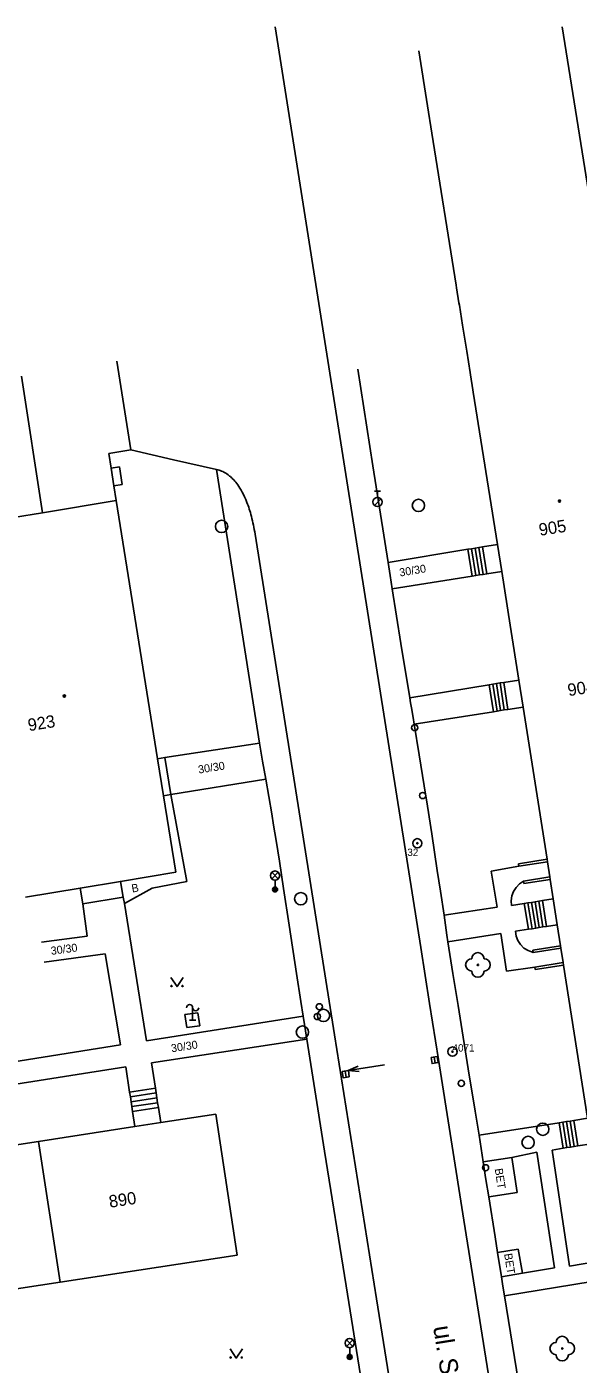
# Model space of a CAD drawing. Extents: x -539244 to -537359, y -1183785 to -1181851.
# Drawn here: x -537635.9 to -537591.1, y -1181981.5 to -1181872.9 of the extents above; entities that cross this region are included whole.
import ezdxf

# ---------------------------------------------------------------- set-up
doc = ezdxf.new("R2010")
doc.units = 0
for name, color, linetype in [('Vrstva 10', 7, 'Continuous'), ('Vrstva 11', 7, 'Continuous'), ('Vrstva 21', 7, 'Continuous'), ('Vrstva 22', 7, 'Continuous'), ('Vrstva 23', 7, 'Continuous'), ('Vrstva 24', 7, 'Continuous'), ('Vrstva 27', 7, 'Continuous'), ('Vrstva 28', 7, 'Continuous'), ('Vrstva 33', 7, 'Continuous'), ('Vrstva 36', 7, 'Continuous'), ('Vrstva 39', 7, 'Continuous'), ('Vrstva 40', 7, 'Continuous'), ('Vrstva 45', 7, 'Continuous'), ('Vrstva 47', 7, 'Continuous'), ('Vrstva 49', 7, 'Continuous'), ('Vrstva 5', 7, 'Continuous'), ('Vrstva 7', 7, 'Continuous')]:
    doc.layers.add(name, color=color, linetype=linetype)

msp = doc.modelspace()

# ---------------------------------------------------------------- linework, layer by layer
at = {"layer": 'Vrstva 10'}
for p, q in [((-537609.825, -1181910.265), (-537615.74, -1181872.87)), ((-537603.91, -1181947.66), (-537609.825, -1181910.265)), ((-537614.135, -1181934.425), (-537617.36, -1181914.09)), ((-537610.91, -1181954.76), (-537614.135, -1181934.425)), ((-537622, -1181952.95), (-537623.06, -1181953.1)), ((-537623.06, -1181953.1), (-537622.91, -1181954.16)), ((-537621.85, -1181954.01), (-537622, -1181952.95)), ((-537622.91, -1181954.16), (-537621.85, -1181954.01)), ((-537607.495, -1181976.195), (-537610.91, -1181954.76)), ((-537601.447, -1181963.276), (-537602.48, -1181956.74)), ((-537600.408, -1181969.81), (-537601.447, -1181963.276)), ((-537598.321, -1181982.879), (-537600.408, -1181969.81)), ((-537604.08, -1181997.63), (-537607.495, -1181976.195))]:
    msp.add_line(p, q, dxfattribs=at)
for points in [[(-537620.49, -1181908.83), (-537623.975, -1181908.035), (-537627.46, -1181907.24)], [(-537617.36, -1181914.09), (-537617.391, -1181913.899), (-537617.425, -1181913.71), (-537617.46, -1181913.524), (-537617.497, -1181913.341), (-537617.535, -1181913.162), (-537617.575, -1181912.988), (-537617.616, -1181912.817), (-537617.658, -1181912.652), (-537617.701, -1181912.491), (-537617.746, -1181912.336), (-537617.79, -1181912.185), (-537617.836, -1181912.04), (-537617.882, -1181911.9), (-537617.929, -1181911.765), (-537617.976, -1181911.635), (-537618.023, -1181911.51), (-537618.119, -1181911.27), (-537618.215, -1181911.051), (-537618.311, -1181910.849), (-537618.406, -1181910.665), (-537618.5, -1181910.497), (-537618.591, -1181910.344), (-537618.681, -1181910.205), (-537618.768, -1181910.079), (-537618.853, -1181909.964), (-537618.935, -1181909.86), (-537619.014, -1181909.766), (-537619.09, -1181909.681), (-537619.163, -1181909.603), (-537619.234, -1181909.533), (-537619.301, -1181909.47), (-537619.366, -1181909.413), (-537619.427, -1181909.361), (-537619.546, -1181909.269), (-537619.653, -1181909.194), (-537619.749, -1181909.133), (-537619.835, -1181909.082), (-537619.912, -1181909.041), (-537619.98, -1181909.007), (-537620.102, -1181908.953), (-537620.196, -1181908.917), (-537620.268, -1181908.892), (-537620.378, -1181908.858), (-537620.49, -1181908.83)], [(-537602.48, -1181956.74), (-537603.195, -1181952.2), (-537603.91, -1181947.66)]]:
    msp.add_lwpolyline(points, dxfattribs=at)
at = {"layer": 'Vrstva 11'}
for p, q in [((-537607.796, -1181908.535), (-537609.03, -1181900.69)), ((-537629.06, -1181908.728), (-537628.37, -1181908.62)), ((-537628.16, -1181910.04), (-537628.37, -1181908.62)), ((-537617.01, -1181931.05), (-537620.49, -1181908.83)), ((-537606.56, -1181916.38), (-537607.796, -1181908.535)), ((-537628.837, -1181910.146), (-537628.16, -1181910.04)), ((-537600.09, -1181915.31), (-537606.56, -1181916.38)), ((-537599.743, -1181917.49), (-537600.09, -1181915.31)), ((-537599.446, -1181917.442), (-537599.793, -1181915.262)), ((-537599.15, -1181917.395), (-537599.497, -1181915.215)), ((-537598.854, -1181917.348), (-537599.201, -1181915.168)), ((-537598.557, -1181917.301), (-537598.904, -1181915.121)), ((-537599.743, -1181917.49), (-537606.22, -1181918.52)), ((-537597.423, -1181928.41), (-537597.767, -1181926.217)), ((-537597.126, -1181928.363), (-537597.47, -1181926.17)), ((-537596.83, -1181928.317), (-537597.174, -1181926.124)), ((-537604.81, -1181927.39), (-537598.36, -1181926.31)), ((-537598.016, -1181928.503), (-537598.36, -1181926.31)), ((-537597.719, -1181928.456), (-537598.063, -1181926.263)), ((-537598.016, -1181928.503), (-537604.44, -1181929.51)), ((-537624.7, -1181932.23), (-537617.01, -1181931.05)), ((-537625.287, -1181932.324), (-537624.7, -1181932.23)), ((-537624.19, -1181935.23), (-537624.7, -1181932.23)), ((-537624.19, -1181935.23), (-537616.49, -1181933.99)), ((-537624.805, -1181935.329), (-537624.19, -1181935.23)), ((-537622.91, -1181942.29), (-537624.19, -1181935.23)), ((-537595.95, -1181941.05), (-537598.2, -1181941.46)), ((-537628.293, -1181942.29), (-537628.08, -1181943.56)), ((-537625.71, -1181942.83), (-537622.91, -1181942.29)), ((-537598.2, -1181941.46), (-537597.71, -1181944.39)), ((-537631.573, -1181942.839), (-537631.36, -1181944.11)), ((-537631.36, -1181944.11), (-537628.08, -1181943.56)), ((-537628.08, -1181943.56), (-537627.97, -1181944.07)), ((-537627.97, -1181944.07), (-537625.71, -1181942.83)), ((-537631.01, -1181946.73), (-537631.36, -1181944.11)), ((-537626.17, -1181955.23), (-537627.97, -1181944.07)), ((-537597.71, -1181944.39), (-537602.02, -1181945.03)), ((-537595.5, -1181944.08), (-537596.55, -1181944.24)), ((-537595.172, -1181946.174), (-537595.5, -1181944.08)), ((-537594.875, -1181946.127), (-537595.203, -1181944.033)), ((-537594.579, -1181946.081), (-537594.907, -1181943.987)), ((-537594.282, -1181946.034), (-537594.61, -1181943.94)), ((-537593.986, -1181945.988), (-537594.314, -1181943.894)), ((-537593.69, -1181945.941), (-537594.018, -1181943.847)), ((-537634.702, -1181947.223), (-537631.01, -1181946.73)), ((-537601.71, -1181947.2), (-537597.4, -1181946.51)), ((-537597.4, -1181946.51), (-537596.96, -1181949.58)), ((-537595.172, -1181946.174), (-537596.23, -1181946.34)), ((-537634.486, -1181948.842), (-537629.53, -1181948.18)), ((-537628.28, -1181955.57), (-537629.53, -1181948.18)), ((-537596.96, -1181949.58), (-537594.64, -1181949.24)), ((-537613.47, -1181953.24), (-537626.17, -1181955.23)), ((-537600.047, -1181957.509), (-537600.884, -1181952.356)), ((-537625.77, -1181957.023), (-537613.173, -1181955.105)), ((-537628.28, -1181955.57), (-537663.657, -1181961.117)), ((-537627.864, -1181957.351), (-537643.514, -1181959.805)), ((-537627.864, -1181957.351), (-537627.552, -1181959.395)), ((-537625.77, -1181957.023), (-537625.457, -1181959.075)), ((-537611.727, -1181964.186), (-537612.601, -1181958.713)), ((-537627.552, -1181959.395), (-537625.457, -1181959.075)), ((-537627.491, -1181959.79), (-537625.396, -1181959.47)), ((-537627.431, -1181960.185), (-537625.336, -1181959.865)), ((-537627.37, -1181960.581), (-537625.275, -1181960.261)), ((-537627.309, -1181960.976), (-537625.214, -1181960.656)), ((-537592.665, -1181961.888), (-537599.18, -1181962.91)), ((-537592.665, -1181961.888), (-537592.34, -1181963.96)), ((-537592.368, -1181961.841), (-537592.043, -1181963.913)), ((-537592.072, -1181961.795), (-537591.747, -1181963.867)), ((-537591.775, -1181961.748), (-537591.45, -1181963.82)), ((-537590.361, -1181961.527), (-537591.479, -1181961.702)), ((-537591.479, -1181961.702), (-537591.154, -1181963.774)), ((-537609.977, -1181975.131), (-537611.727, -1181964.186)), ((-537592.34, -1181963.96), (-537593.25, -1181964.11)), ((-537593.25, -1181964.11), (-537591.84, -1181973.53)), ((-537590.036, -1181963.599), (-537591.154, -1181963.774)), ((-537596.52, -1181964.7), (-537598.84, -1181965.06)), ((-537594.48, -1181964.28), (-537596.52, -1181964.7)), ((-537596.076, -1181967.561), (-537596.52, -1181964.7)), ((-537593.04, -1181973.66), (-537594.48, -1181964.28)), ((-537596.076, -1181967.561), (-537598.39, -1181967.92)), ((-537597.677, -1181972.419), (-537595.99, -1181972.15)), ((-537595.655, -1181974.108), (-537595.99, -1181972.15)), ((-537591.84, -1181973.53), (-537587.91, -1181972.88)), ((-537597.11, -1181975.95), (-537587.661, -1181974.387)), ((-537608.814, -1181982.429), (-537609.977, -1181975.131)), ((-537595.086, -1181988.527), (-537597.11, -1181975.95))]:
    msp.add_line(p, q, dxfattribs=at)
for points in [[(-537597.682, -1181914.927), (-537598.904, -1181915.121), (-537599.201, -1181915.168), (-537599.497, -1181915.215), (-537599.793, -1181915.262), (-537600.09, -1181915.31)], [(-537605.515, -1181922.955), (-537606.22, -1181918.52), (-537606.39, -1181917.45), (-537606.56, -1181916.38)], [(-537597.336, -1181917.107), (-537598.557, -1181917.301), (-537598.854, -1181917.348), (-537599.15, -1181917.395), (-537599.446, -1181917.442), (-537599.743, -1181917.49)], [(-537604.032, -1181932.014), (-537604.44, -1181929.51), (-537604.531, -1181928.98), (-537604.674, -1181928.185), (-537604.744, -1181927.788), (-537604.81, -1181927.39), (-537605.515, -1181922.955)], [(-537595.942, -1181925.931), (-537597.174, -1181926.124), (-537597.47, -1181926.17), (-537597.767, -1181926.217), (-537598.063, -1181926.263), (-537598.36, -1181926.31)], [(-537595.598, -1181928.124), (-537596.83, -1181928.317), (-537597.126, -1181928.363), (-537597.423, -1181928.41), (-537597.719, -1181928.456), (-537598.016, -1181928.503)], [(-537616.49, -1181933.99), (-537616.75, -1181932.52), (-537617.01, -1181931.05)], [(-537602.311, -1181943.088), (-537602.568, -1181941.39), (-537603.023, -1181938.418), (-537603.369, -1181936.189), (-537603.632, -1181934.519), (-537604.032, -1181932.014)], [(-537614.602, -1181945.828), (-537615.049, -1181942.865), (-537615.392, -1181940.643), (-537615.654, -1181938.978), (-537615.856, -1181937.73), (-537616.01, -1181936.794), (-537616.246, -1181935.391), (-537616.49, -1181933.99)], [(-537595.58, -1181942.26), (-537595.902, -1181942.485), (-537596.172, -1181942.77), (-537596.378, -1181943.103), (-537596.513, -1181943.472), (-537596.57, -1181943.86), (-537596.55, -1181944.24)], [(-537600.884, -1181952.356), (-537601.3, -1181949.778), (-537601.71, -1181947.2), (-537601.791, -1181946.658), (-537601.905, -1181945.844), (-537601.961, -1181945.437), (-537602.02, -1181945.03), (-537602.311, -1181943.088)], [(-537593.154, -1181943.712), (-537594.018, -1181943.847), (-537594.314, -1181943.894), (-537594.61, -1181943.94), (-537594.907, -1181943.987), (-537595.203, -1181944.033), (-537595.5, -1181944.08)], [(-537613.47, -1181953.24), (-537613.659, -1181952.037), (-537614.006, -1181949.78), (-537614.602, -1181945.828)], [(-537596.23, -1181946.34), (-537596.163, -1181946.726), (-537596.019, -1181947.091), (-537595.804, -1181947.419), (-537595.528, -1181947.696), (-537595.2, -1181947.912), (-537594.79, -1181948.07)], [(-537592.826, -1181945.806), (-537593.69, -1181945.941), (-537593.986, -1181945.988), (-537594.282, -1181946.034), (-537594.579, -1181946.081), (-537594.875, -1181946.127), (-537595.172, -1181946.174)], [(-537612.601, -1181958.713), (-537613.173, -1181955.105), (-537613.47, -1181953.24)], [(-537598.615, -1181966.49), (-537598.84, -1181965.06), (-537599.01, -1181963.985), (-537599.18, -1181962.91), (-537599.493, -1181960.946), (-537600.047, -1181957.509)], [(-537627.552, -1181959.395), (-537627.491, -1181959.79), (-537627.431, -1181960.185), (-537627.37, -1181960.581), (-537627.309, -1181960.976), (-537627.123, -1181962.203)], [(-537625.457, -1181959.075), (-537625.396, -1181959.47), (-537625.336, -1181959.865), (-537625.275, -1181960.261), (-537625.214, -1181960.656), (-537625.028, -1181961.882)], [(-537591.479, -1181961.702), (-537591.775, -1181961.748), (-537592.072, -1181961.795), (-537592.368, -1181961.841), (-537592.665, -1181961.888)], [(-537591.154, -1181963.774), (-537591.45, -1181963.82), (-537591.747, -1181963.867), (-537592.043, -1181963.913), (-537592.34, -1181963.96)], [(-537597.11, -1181975.95), (-537597.235, -1181975.175), (-537597.36, -1181974.4), (-537597.677, -1181972.419), (-537597.877, -1181971.16), (-537598.39, -1181967.92), (-537598.615, -1181966.49)], [(-537597.36, -1181974.4), (-537595.655, -1181974.108), (-537593.04, -1181973.66)]]:
    msp.add_lwpolyline(points, dxfattribs=at)
at = {"layer": 'Vrstva 21'}
for centre, radius in [((-537604.19, -1181939.19), 0.375), ((-537604.19, -1181939.19), 0.05), ((-537601.33, -1181956.11), 0.375), ((-537601.33, -1181956.11), 0.05)]:
    msp.add_circle(centre, radius, dxfattribs=at)
at = {"layer": 'Vrstva 22'}
for centre in [(-537599.27, -1181949.07), (-537592.42, -1181980.23)]:
    msp.add_circle(centre, 0.05, dxfattribs=at)
for centre, start, end in [((-537599.77, -1181949.07), 90, 270), ((-537599.27, -1181948.57), 0, 180), ((-537598.77, -1181949.07), 270, 90), ((-537599.27, -1181949.57), 180, 0), ((-537592.42, -1181979.73), 0, 180), ((-537592.92, -1181980.23), 90, 270), ((-537591.92, -1181980.23), 270, 90), ((-537592.42, -1181980.73), 180, 0)]:
    msp.add_arc(centre, 0.5, start, end, dxfattribs=at)
at = {"layer": 'Vrstva 24'}
for p, q in [((-537622.432, -1181953.545), (-537622.432, -1181952.545)), ((-537622.182, -1181953.545), (-537622.682, -1181953.545))]:
    msp.add_line(p, q, dxfattribs=at)
for centre, start, end in [((-537622.682, -1181952.545), 0, 180), ((-537622.182, -1181952.545), 180, 0)]:
    msp.add_arc(centre, 0.25, start, end, dxfattribs=at)
at = {"layer": 'Vrstva 27'}
for p, q in [((-537602.817, -1181956.548), (-537602.739, -1181957.042)), ((-537609.958, -1181958.192), (-537610.036, -1181957.698))]:
    msp.add_line(p, q, dxfattribs=at)
for points in [[(-537603.064, -1181956.587), (-537602.986, -1181957.081), (-537602.492, -1181957.003), (-537602.57, -1181956.509)], [(-537609.711, -1181958.153), (-537609.789, -1181957.659), (-537610.283, -1181957.737), (-537610.205, -1181958.231)]]:
    msp.add_lwpolyline(points, close=True, dxfattribs=at)
for centre in [(-537604.1, -1181911.75), (-537620.08, -1181913.45), (-537613.65, -1181943.69), (-537611.8, -1181953.17), (-537613.52, -1181954.53), (-537594, -1181962.42), (-537595.19, -1181963.49)]:
    msp.add_circle(centre, 0.5, dxfattribs=at)
at = {"layer": 'Vrstva 28'}
for p, q in [((-537607.67, -1181910.595), (-537607.17, -1181910.595)), ((-537607.42, -1181911.095), (-537607.42, -1181910.595)), ((-537607.678, -1181911.742), (-537607.148, -1181911.212))]:
    msp.add_line(p, q, dxfattribs=at)
for centre, radius in [((-537607.42, -1181911.47), 0.375), ((-537604.4, -1181929.8), 0.25), ((-537603.75, -1181935.31), 0.25), ((-537612.14, -1181952.47), 0.25), ((-537612.31, -1181953.26), 0.25), ((-537600.62, -1181958.69), 0.25), ((-537598.65, -1181965.55), 0.25)]:
    msp.add_circle(centre, radius, dxfattribs=at)
at = {"layer": 'Vrstva 33'}
for p, q in [((-537616.005, -1181942.08), (-537615.475, -1181941.55)), ((-537616.005, -1181941.55), (-537615.475, -1181942.08)), ((-537615.74, -1181942.19), (-537615.74, -1181942.94)), ((-537609.945, -1181980.05), (-537609.415, -1181979.52)), ((-537609.945, -1181979.52), (-537609.415, -1181980.05)), ((-537609.68, -1181980.16), (-537609.68, -1181980.91))]:
    msp.add_line(p, q, dxfattribs=at)
for centre, radius in [((-537615.74, -1181941.815), 0.375), ((-537615.74, -1181942.94), 0.2), ((-537615.74, -1181942.94), 0.145), ((-537615.74, -1181942.94), 0.0876), ((-537609.68, -1181979.785), 0.375), ((-537609.68, -1181980.91), 0.2), ((-537609.68, -1181980.91), 0.145), ((-537609.68, -1181980.91), 0.0876)]:
    msp.add_circle(centre, radius, dxfattribs=at)
at = {"layer": 'Vrstva 36'}
for points in [[(-537624.202, -1181950.082), (-537623.702, -1181950.832), (-537623.202, -1181950.082)], [(-537619.392, -1181980.253), (-537618.892, -1181981.003), (-537618.392, -1181980.253)]]:
    msp.add_lwpolyline(points, dxfattribs=at)
for centre in [(-537624.152, -1181950.782), (-537623.253, -1181950.782), (-537619.342, -1181980.953), (-537618.443, -1181980.953)]:
    msp.add_circle(centre, 0.05, dxfattribs=at)
at = {"layer": 'Vrstva 39'}
for centre, radius in [((-537592.645, -1181911.399), 0.09), ((-537592.645, -1181911.399), 0.0398), ((-537632.851, -1181927.236), 0.09), ((-537632.851, -1181927.236), 0.0398)]:
    msp.add_circle(centre, radius, dxfattribs=at)
at = {"layer": 'Vrstva 45'}
msp.add_line((-537606.847, -1181957.18), (-537609.81, -1181957.65), dxfattribs=at)
msp.add_lwpolyline([(-537608.909, -1181957.74), (-537609.81, -1181957.65), (-537608.981, -1181957.286)], dxfattribs=at)
at = {"layer": 'Vrstva 5'}
for p, q in [((-537592.42, -1181872.87), (-537577.57, -1181966.26)), ((-537627.46, -1181907.24), (-537628.59, -1181900.04)), ((-537634.62, -1181912.34), (-537636.34, -1181901.256)), ((-537629.249, -1181907.521), (-537627.46, -1181907.24)), ((-537634.62, -1181912.34), (-537628.65, -1181911.34)), ((-537618.81, -1181972.65), (-537620.56, -1181961.2)), ((-537633.203, -1181974.85), (-537634.953, -1181963.4)), ((-537633.203, -1181974.85), (-537618.81, -1181972.65)), ((-537650.947, -1181977.562), (-537633.203, -1181974.85))]:
    msp.add_line(p, q, dxfattribs=at)
for points in [[(-537604.06, -1181874.83), (-537603.351, -1181879.29), (-537602.998, -1181881.505), (-537601.031, -1181893.868), (-537601, -1181894.066), (-537600.805, -1181895.297), (-537600.773, -1181895.494), (-537600.517, -1181897.108), (-537600.18, -1181899.226), (-537599.905, -1181900.952), (-537599.874, -1181901.15), (-537599.682, -1181902.355), (-537599.65, -1181902.552), (-537597.682, -1181914.927), (-537597.336, -1181917.107), (-537596.64, -1181921.48)], [(-537629.249, -1181907.521), (-537629.06, -1181908.728), (-537628.837, -1181910.146), (-537628.65, -1181911.34)], [(-537623.81, -1181941.54), (-537624.805, -1181935.329), (-537625.287, -1181932.324), (-537628.65, -1181911.34)], [(-537637.62, -1181912.82), (-537637.566, -1181912.812), (-537636.986, -1181912.724), (-537634.62, -1181912.34)], [(-537596.64, -1181921.48), (-537595.942, -1181925.931), (-537595.598, -1181928.124), (-537593.659, -1181940.488), (-537593.629, -1181940.686), (-537593.434, -1181941.924), (-537593.403, -1181942.121), (-537593.154, -1181943.712), (-537592.826, -1181945.806), (-537592.556, -1181947.517), (-537592.526, -1181947.715), (-537592.344, -1181948.88), (-537592.313, -1181949.077), (-537590.361, -1181961.527), (-537590.036, -1181963.599), (-537589.33, -1181968.1)], [(-537636, -1181943.58), (-537631.573, -1181942.839), (-537628.293, -1181942.29), (-537623.81, -1181941.54)], [(-537634.953, -1181963.4), (-537627.123, -1181962.203), (-537625.028, -1181961.882), (-537620.56, -1181961.2)], [(-537652.697, -1181966.112), (-537644.867, -1181964.915), (-537642.782, -1181964.596), (-537634.953, -1181963.4)]]:
    msp.add_lwpolyline(points, dxfattribs=at)
at = {"layer": 'Vrstva 7'}
for p, q in [((-537593.659, -1181940.488), (-537595.98, -1181940.852)), ((-537595.98, -1181940.852), (-537595.95, -1181941.05)), ((-537593.629, -1181940.686), (-537595.95, -1181941.05)), ((-537593.434, -1181941.924), (-537595.58, -1181942.26)), ((-537595.58, -1181942.26), (-537595.549, -1181942.457)), ((-537593.403, -1181942.121), (-537595.549, -1181942.457)), ((-537592.556, -1181947.517), (-537594.82, -1181947.872)), ((-537594.82, -1181947.872), (-537594.79, -1181948.07)), ((-537592.526, -1181947.715), (-537594.79, -1181948.07)), ((-537592.344, -1181948.88), (-537594.64, -1181949.24)), ((-537594.64, -1181949.24), (-537594.609, -1181949.437)), ((-537592.313, -1181949.077), (-537594.609, -1181949.437))]:
    msp.add_line(p, q, dxfattribs=at)

# ---------------------------------------------------------------- texts
at = {"layer": 'Vrstva 23'}
for s, p in [('32', (-537605.001, -1181940.223)), ('4071', (-537601.33, -1181956.11))]:
    msp.add_text(s, height=0.6, dxfattribs=at).set_placement(p)
at = {"layer": 'Vrstva 40'}
for s, rotation, p in [('30/30', 9.39051, (-537605.592, -1181917.528)), ('30/30', 9.14831, (-537621.932, -1181933.533)), ('B', 9.50043, (-537627.338, -1181943.192)), ('30/30', 7.60828, (-537633.908, -1181948.255)), ('30/30', 8.65602, (-537624.136, -1181956.171)), ('BET', 278.93323, (-537597.908, -1181965.639)), ('BET', 279.10223, (-537597.144, -1181972.547))]:
    msp.add_text(s, height=0.65, rotation=rotation, dxfattribs=at).set_placement(p)
at = {"layer": 'Vrstva 47'}
for s, rotation, p in [(' 905', 9.03758, (-537594.607, -1181914.284)), (' 904', 8.9114, (-537592.275, -1181927.306)), (' 923', 9.10508, (-537636.101, -1181930.149)), (' 890', 8.68975, (-537629.521, -1181968.855))]:
    msp.add_text(s, height=1, rotation=rotation, dxfattribs=at).set_placement(p)
at = {"layer": 'Vrstva 49'}
msp.add_text('ul. Svatováclavská', height=1.5, rotation=279.05222, dxfattribs=at).set_placement((-537602.908, -1181978.469))

doc.saveas('drawing.dxf')
